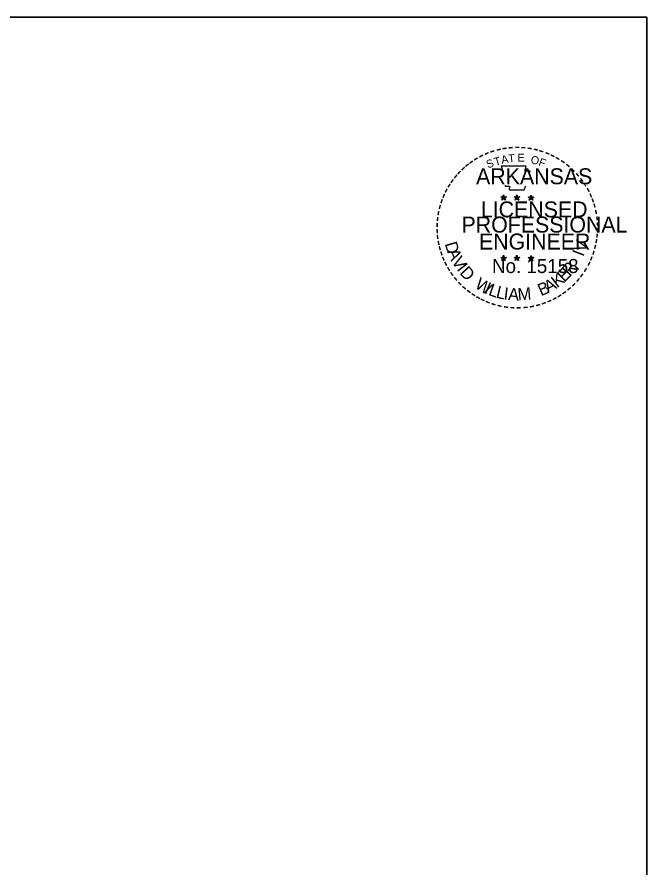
# Model space of a CAD drawing. Extents: x 31847 to 33828, y 52928 to 59118.
# Drawn here: x 33172 to 33579, y 53478 to 54028 of the extents above; entities that cross this region are included whole.
import ezdxf

# ---------------------------------------------------------------- set-up
doc = ezdxf.new("R2010")
doc.units = 0
for name, color, linetype in [('Default', 7, 'Continuous'), ('DSN_DRFT_Junk-No-Plot', 7, 'Continuous'), ('R_Border PE', 7, 'Continuous')]:
    doc.layers.add(name, color=color, linetype=linetype)

msp = doc.modelspace()

# ---------------------------------------------------------------- linework, layer by layer
at = {"layer": 'Default'}
msp.add_lwpolyline([(31878.87, 54027.5), (31878.87, 52927.5), (33578.87, 52927.5), (33578.87, 54027.5)], close=True, dxfattribs=at)
at = {"layer": 'DSN_DRFT_Junk-No-Plot'}
msp.add_lwpolyline([(31878.87, 54027.5), (33578.87, 54027.5), (33578.87, 52927.5), (31878.87, 52927.5)], close=True, dxfattribs=at)
at = {"layer": 'R_Border PE'}
for p, q in [((33484.44, 53911.21), (33486.24, 53910.64)), ((33484.44, 53911.21), (33485.74, 53910.98)), ((33484.44, 53911.21), (33485.66, 53910.58)), ((33486.24, 53912.52), (33486.02, 53911.22)), ((33486.24, 53910.64), (33486.24, 53912.52)), ((33486.24, 53912.52), (33486.49, 53911.23)), ((33488.03, 53911.21), (33486.24, 53910.64)), ((33488.03, 53911.21), (33486.55, 53910.96)), ((33488.03, 53911.21), (33486.97, 53910.69)), ((33493.05, 53911.21), (33494.85, 53910.64)), ((33493.05, 53911.21), (33494.35, 53910.98)), ((33493.05, 53911.21), (33494.27, 53910.58)), ((33494.85, 53912.52), (33494.64, 53911.22)), ((33494.85, 53910.64), (33494.85, 53912.52)), ((33494.85, 53912.52), (33495.1, 53911.23)), ((33496.64, 53911.21), (33494.85, 53910.64)), ((33496.64, 53911.21), (33495.16, 53910.96)), ((33496.64, 53911.21), (33495.58, 53910.69)), ((33502.14, 53911.15), (33503.94, 53910.58)), ((33502.14, 53911.15), (33503.45, 53910.92)), ((33502.14, 53911.15), (33503.37, 53910.52)), ((33503.94, 53912.46), (33503.73, 53911.16)), ((33503.94, 53910.58), (33503.94, 53912.46)), ((33503.94, 53912.46), (33504.2, 53911.17)), ((33505.73, 53911.15), (33503.94, 53910.58)), ((33505.73, 53911.15), (33504.26, 53910.9)), ((33505.73, 53911.15), (33504.68, 53910.63)), ((33485.12, 53909.11), (33486.24, 53910.64)), ((33485.12, 53909.11), (33485.77, 53910.37)), ((33485.12, 53909.11), (33486.23, 53910.23)), ((33487.33, 53909.11), (33486.23, 53910.21)), ((33487.33, 53909.11), (33486.24, 53910.64)), ((33487.33, 53909.11), (33486.63, 53910.61)), ((33493.73, 53909.11), (33494.85, 53910.64)), ((33493.73, 53909.11), (33494.38, 53910.37)), ((33493.73, 53909.11), (33494.84, 53910.23)), ((33495.95, 53909.11), (33494.84, 53910.21)), ((33495.95, 53909.11), (33494.85, 53910.64)), ((33495.95, 53909.11), (33495.24, 53910.61)), ((33502.83, 53909.05), (33503.94, 53910.58)), ((33502.83, 53909.05), (33503.48, 53910.31)), ((33502.83, 53909.05), (33503.93, 53910.17)), ((33505.04, 53909.05), (33503.93, 53910.15)), ((33505.04, 53909.05), (33503.94, 53910.58)), ((33505.04, 53909.05), (33504.33, 53910.55)), ((33486.22, 53873.48), (33486, 53872.18)), ((33486.22, 53871.59), (33486.22, 53873.48)), ((33486.22, 53873.48), (33486.47, 53872.19)), ((33494.82, 53873.48), (33494.61, 53872.18)), ((33494.82, 53871.59), (33494.82, 53873.48)), ((33494.82, 53873.48), (33495.07, 53872.19)), ((33503.93, 53873.42), (33503.72, 53872.12)), ((33503.93, 53871.54), (33503.93, 53873.42)), ((33503.93, 53873.42), (33504.18, 53872.13)), ((33484.42, 53872.17), (33486.22, 53871.59)), ((33484.42, 53872.17), (33485.72, 53871.93)), ((33484.42, 53872.17), (33485.64, 53871.54)), ((33485.1, 53870.06), (33486.22, 53871.59)), ((33485.1, 53870.06), (33485.75, 53871.32)), ((33485.1, 53870.06), (33486.21, 53871.18)), ((33487.31, 53870.06), (33486.21, 53871.17)), ((33488, 53872.17), (33486.22, 53871.59)), ((33487.31, 53870.06), (33486.22, 53871.59)), ((33488, 53872.17), (33486.53, 53871.91)), ((33487.31, 53870.06), (33486.61, 53871.56)), ((33488, 53872.17), (33486.95, 53871.64)), ((33493.02, 53872.17), (33494.82, 53871.59)), ((33493.02, 53872.17), (33494.33, 53871.93)), ((33493.02, 53872.17), (33494.24, 53871.54)), ((33493.71, 53870.06), (33494.82, 53871.59)), ((33493.71, 53870.06), (33494.36, 53871.32)), ((33493.71, 53870.06), (33494.81, 53871.18)), ((33495.92, 53870.06), (33494.81, 53871.17)), ((33496.61, 53872.17), (33494.82, 53871.59)), ((33495.92, 53870.06), (33494.82, 53871.59)), ((33496.61, 53872.17), (33495.14, 53871.91)), ((33495.92, 53870.06), (33495.21, 53871.56)), ((33496.61, 53872.17), (33495.56, 53871.64)), ((33502.13, 53872.11), (33503.93, 53871.54)), ((33502.13, 53872.11), (33503.44, 53871.88)), ((33502.13, 53872.11), (33503.35, 53871.49)), ((33502.82, 53870.01), (33503.93, 53871.54)), ((33502.82, 53870.01), (33503.47, 53871.27)), ((33502.82, 53870.01), (33503.92, 53871.13)), ((33505.03, 53870.01), (33503.92, 53871.11)), ((33505.72, 53872.11), (33503.93, 53871.54)), ((33505.03, 53870.01), (33503.93, 53871.54)), ((33505.72, 53872.11), (33504.25, 53871.86)), ((33505.03, 53870.01), (33504.32, 53871.51)), ((33505.72, 53872.11), (33504.67, 53871.59))]:
    msp.add_line(p, q, dxfattribs=at)
for points in [[(33484.65, 53931.21), (33486.03, 53926.95)], [(33502.75, 53926.46), (33503.48, 53927.92), (33499.95, 53927.8), (33500.71, 53931.21), (33484.65, 53931.21)], [(33487.18, 53918.72), (33487.18, 53918.27), (33490.09, 53918.17), (33489.81, 53915.73), (33499.45, 53915.73), (33500.49, 53918.49)], [(33486.24, 53912.52), (33487.33, 53909.11), (33484.44, 53911.21), (33488.03, 53911.21), (33485.12, 53909.11), (33486.24, 53912.52)], [(33494.85, 53912.52), (33495.95, 53909.11), (33493.05, 53911.21), (33496.64, 53911.21), (33493.73, 53909.11), (33494.85, 53912.52)], [(33503.94, 53912.46), (33505.04, 53909.05), (33502.14, 53911.15), (33505.73, 53911.15), (33502.83, 53909.05), (33503.94, 53912.46)], [(33486.22, 53873.48), (33487.31, 53870.06), (33484.42, 53872.17), (33488, 53872.17), (33485.1, 53870.06), (33486.22, 53873.48)], [(33494.82, 53873.48), (33495.92, 53870.06), (33493.02, 53872.17), (33496.61, 53872.17), (33493.71, 53870.06), (33494.82, 53873.48)], [(33503.93, 53873.42), (33505.03, 53870.01), (33502.13, 53872.11), (33505.72, 53872.11), (33502.82, 53870.01), (33503.93, 53873.42)]]:
    msp.add_lwpolyline(points, dxfattribs=at)
for centre, radius in [((33486.23, 53910.64), 0.888), ((33486.23, 53910.64), 0.745), ((33486.23, 53910.64), 0.597), ((33486.23, 53910.64), 0.511), ((33486.23, 53910.64), 0.385), ((33494.84, 53910.64), 0.888), ((33494.84, 53910.64), 0.745), ((33494.84, 53910.64), 0.597), ((33494.84, 53910.64), 0.511), ((33494.84, 53910.64), 0.385), ((33503.94, 53910.58), 0.888), ((33503.94, 53910.58), 0.745), ((33503.94, 53910.58), 0.597), ((33503.94, 53910.58), 0.511), ((33486.23, 53910.64), 0.255), ((33486.23, 53910.64), 0.153), ((33494.84, 53910.64), 0.255), ((33494.84, 53910.64), 0.153), ((33503.94, 53910.58), 0.385), ((33503.94, 53910.58), 0.255), ((33503.94, 53910.58), 0.153), ((33486.21, 53871.59), 0.888), ((33486.21, 53871.59), 0.745), ((33486.21, 53871.59), 0.597), ((33486.21, 53871.59), 0.511), ((33486.21, 53871.59), 0.385), ((33486.21, 53871.59), 0.255), ((33486.21, 53871.59), 0.153), ((33494.82, 53871.59), 0.888), ((33494.82, 53871.59), 0.745), ((33494.82, 53871.59), 0.597), ((33494.82, 53871.59), 0.511), ((33494.82, 53871.59), 0.385), ((33494.82, 53871.59), 0.255), ((33494.82, 53871.59), 0.153), ((33503.93, 53871.54), 0.888), ((33503.93, 53871.54), 0.745), ((33503.93, 53871.54), 0.597), ((33503.93, 53871.54), 0.511), ((33503.93, 53871.54), 0.385), ((33503.93, 53871.54), 0.255), ((33503.93, 53871.54), 0.153)]:
    msp.add_circle(centre, radius, dxfattribs=at)

# ---------------------------------------------------------------- texts
for s, height, rotation, p in [('-', 8.25, 28.7918, (33471.66, 53934)), ('-', 8.25, 24.3072, (33474.92, 53935.63)), ('-', 8.25, 19.1761, (33478.19, 53937.02)), ('-', 8.25, 13.6302, (33482.06, 53938.26)), ('-', 8.25, 10.2193, (33485.55, 53939.1)), ('T', 5.16, 6.0228, (33489.51, 53933.41)), ('-', 8.25, 5.8968, (33489.31, 53939.67)), ('-', 8.25, 0.1862, (33493.29, 53940.04)), ('E', 5.16, 0.8323, (33495.21, 53933.97)), ('-', 8.25, 357.743, (33497.02, 53939.97)), ('-', 8.25, 352.1617, (33500.86, 53939.68)), ('-', 8.25, 347.2049, (33504.57, 53939.09)), ('-', 8.25, 342.3362, (33507.84, 53938.29)), ('-', 8.25, 337.8551, (33511.63, 53937.14)), ('-', 8.25, 334.1211, (33514.88, 53935.75)), ('-', 8.25, 36.2317, (33465.6, 53930.05)), ('-', 8.25, 34.0636, (33468.58, 53932.09)), ('S', 5.16, 21.594, (33476.16, 53929.55)), ('T', 5.16, 16.4036, (33480.88, 53931.26)), ('A', 5.16, 11.2132, (33485.14, 53932.55)), ('O', 5.16, 350.4515, (33503.48, 53932.89)), ('F', 5.16, 340.0707, (33508.4, 53931.72)), ('-', 8.25, 329.6409, (33517.87, 53934.29)), ('-', 8.25, 325.8627, (33521.18, 53932.43)), ('-', 8.25, 48.4231, (33458.6, 53923.49)), ('-', 8.25, 42.9622, (33460.91, 53925.96)), ('-', 8.25, 38.9507, (33463.15, 53928.11)), ('-', 8.25, 320.5297, (33524.33, 53930.23)), ('-', 8.25, 315.5786, (33527.42, 53927.71)), ('-', 8.25, 54.2325, (33454.4, 53918.06)), ('-', 8.25, 50.6142, (33456.52, 53920.99)), ('-', 8.25, 309.8797, (33530.35, 53924.88)), ('-', 8.25, 306.6522, (33533.06, 53921.77)), ('-', 8.25, 62.8713, (33451.11, 53912.18)), ('-', 8.25, 58.0706, (33452.72, 53915.34)), ('-', 7.22, 303.6753, (33535.56, 53918.85)), ('-', 8.25, 299.6684, (33537.21, 53915.72)), ('-', 8.25, 67.7743, (33449.77, 53909.03)), ('-', 8.25, 294.6628, (33538.88, 53912.56)), ('-', 8.25, 75.461, (33447.62, 53902.1)), ('-', 8.25, 72.3945, (33448.64, 53905.78)), ('-', 8.25, 290.5728, (33540.21, 53909.58)), ('-', 8.25, 285.1233, (33541.41, 53906.59)), ('-', 8.25, 81.2013, (33446.94, 53898.42)), ('-', 8.25, 280.5493, (33542.44, 53902.77)), ('-', 8.25, 85.1863, (33446.55, 53894.86)), ('-', 8.25, 276.5962, (33543.28, 53898.81)), ('-', 8.25, 274.3301, (33543.59, 53895.09)), ('-', 8.25, 94.1959, (33446.6, 53887.51)), ('-', 8.25, 89.0622, (33446.42, 53891.24)), ('-', 8.25, 269.9407, (33543.76, 53891.83)), ('-', 8.25, 98.9479, (33446.98, 53884.07)), ('V', 7.94, 72.6573, (33538.84, 53875.01)), ('-', 8.25, 260.9953, (33543.3, 53885.02)), ('-', 8.25, 263.5172, (33543.67, 53888.39)), ('-', 8.25, 101.7149, (33447.67, 53880.29)), ('-', 8.25, 105.4578, (33448.51, 53877.22)), ('D', 7.94, 286.2848, (33448.13, 53881)), ('-', 8.25, 255.7626, (33542.73, 53881.52)), ('-', 8.25, 109.0874, (33449.62, 53873.97)), ('-', 8.25, 114.0643, (33450.92, 53870.89)), ('A', 7.94, 292.7835, (33449.64, 53875.83)), ('V', 7.94, 300.7936, (33452.29, 53869.75)), ('I', 7.94, 69.0301, (33537.69, 53872.24)), ('-', 8.25, 247.8887, (33540.65, 53874.34)), ('-', 8.25, 252.8681, (33541.8, 53877.81)), ('-', 8.25, 115.7289, (33452.5, 53867.71)), ('I', 7.94, 308.3502, (33455.54, 53864.41)), ('R', 7.94, 50.3651, (33529.18, 53859.4)), ('-', 8.25, 244.6197, (33539.3, 53871.1)), ('-', 8.25, 120.4471, (33454.34, 53864.68)), ('-', 8.25, 125.8934, (33456.42, 53861.79)), ('D', 7.94, 311.9774, (33457.35, 53862)), ('K', 7.94, 36.9143, (33520.71, 53852.19)), ('E', 7.94, 44.0175, (33525.4, 53855.75)), (',', 7.94, 57.4684, (33532.91, 53863.95)), ('-', 8.25, 233.8452, (33535.19, 53863.85)), ('-', 8.25, 239.0712, (33537.27, 53867.22)), ('-', 8.25, 130.7181, (33458.8, 53858.95)), ('-', 8.25, 134.2238, (33461.46, 53856.13)), ('W', 7.94, 328.0731, (33467.04, 53852.9)), ('I', 7.94, 336.6877, (33473.16, 53849.24)), ('B', 7.94, 22.8589, (33510.33, 53846.98)), ('A', 7.94, 28.9042, (33514.95, 53848.91)), ('-', 8.25, 231.2538, (33532.98, 53860.94)), ('-', 8.25, 138.9338, (33464.17, 53853.74)), ('-', 8.25, 144.6463, (33467.04, 53851.65)), ('L', 7.94, 340.3149, (33475.89, 53847.98)), ('L', 7.94, 346.6625, (33480.84, 53846.2)), ('I', 7.94, 353.0101, (33485.95, 53844.98)), ('A', 7.94, 356.6373, (33488.92, 53844.54)), ('M', 7.94, 4.6473, (33495.55, 53844.24)), ('-', 8.25, 221.0851, (33527.81, 53855.4)), ('-', 8.25, 225.7653, (33530.51, 53858.03)), ('-', 8.25, 148.0898, (33469.93, 53849.74)), ('-', 8.25, 151.5704, (33472.92, 53848.06)), ('-', 8.25, 154.6002, (33475.61, 53846.79)), ('-', 8.25, 207.3568, (33519.35, 53849.19)), ('-', 8.25, 212.2491, (33522.23, 53850.97)), ('-', 8.25, 215.7363, (33524.98, 53852.97)), ('-', 8.25, 158.5612, (33478.83, 53845.48)), ('-', 8.25, 162.7983, (33482.37, 53844.38)), ('-', 8.25, 167.5555, (33486.05, 53843.53)), ('-', 8.25, 173.1155, (33490.04, 53842.97)), ('-', 8.25, 176.5183, (33493.89, 53842.69)), ('-', 8.25, 181.5918, (33497.73, 53842.79)), ('-', 8.25, 185.8167, (33501.9, 53843.18)), ('-', 8.25, 191.2858, (33505.69, 53843.86)), ('-', 8.25, 195.4743, (33509.45, 53844.89)), ('-', 8.25, 199.4643, (33512.88, 53846.11)), ('-', 8.25, 204.2516, (33516.14, 53847.54))]:
    msp.add_text(s, height=height, rotation=rotation, dxfattribs=at).set_placement(p)
for s, height, p in [('ARKANSAS', 10.312, (33468.42, 53919.41)), ('LICENSED', 10.312, (33471.5, 53898.02)), ('PROFESSIONAL', 10.3125, (33459, 53888.2)), ('ENGINEER', 10.312, (33470.28, 53877.24)), ('No. 15158', 9.06, (33478.74, 53862.03)), ('AAMU', 0.000103, (33494.48, 53844.22))]:
    msp.add_text(s, height=height, dxfattribs=at).set_placement(p)

doc.saveas('drawing.dxf')
